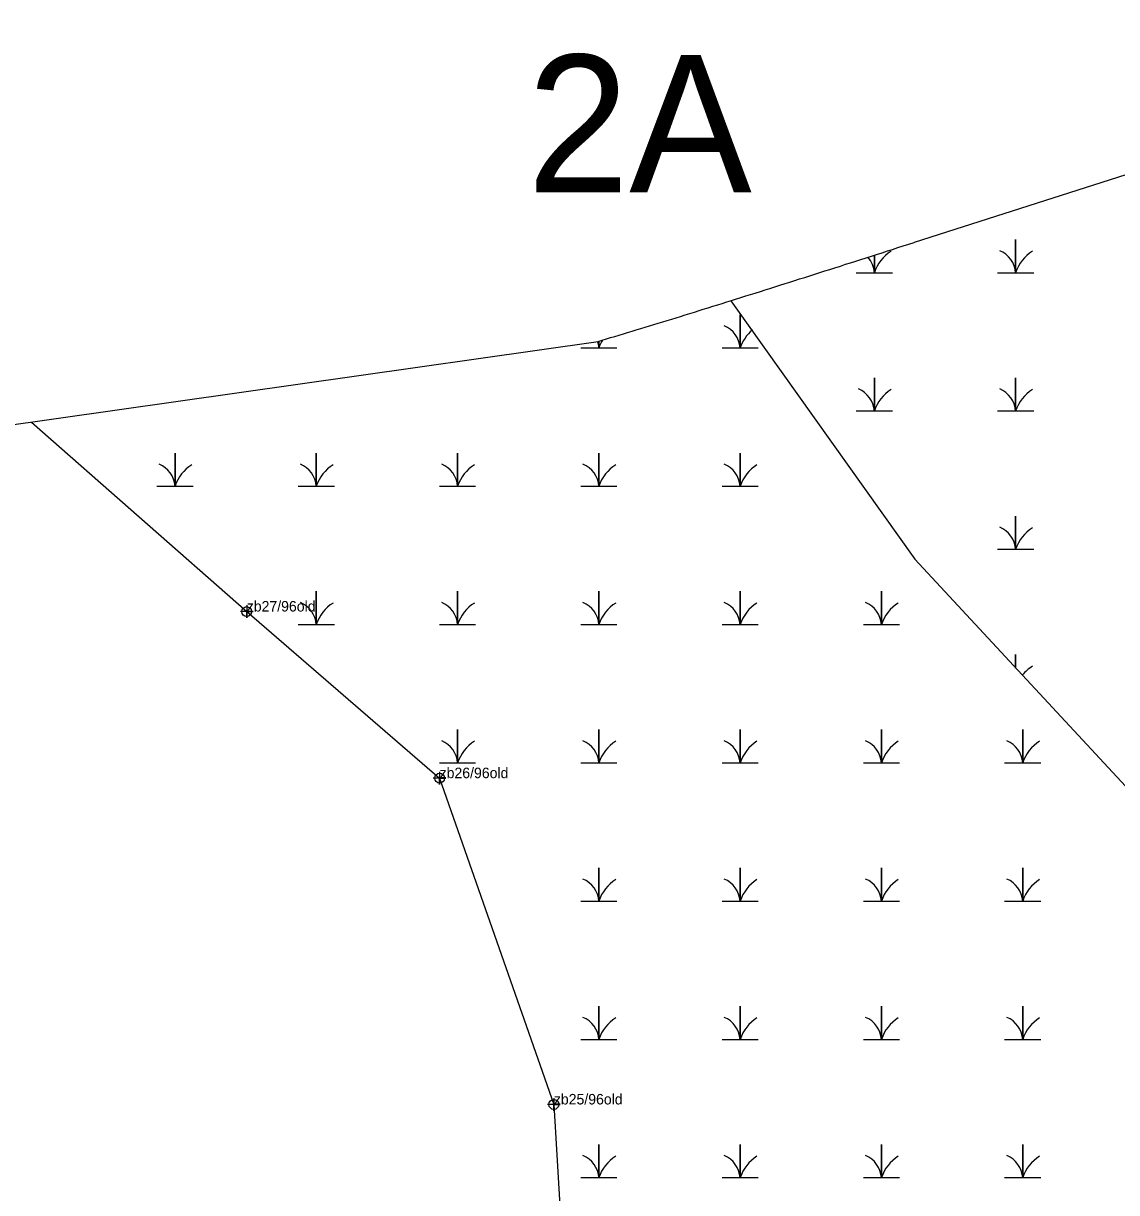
# Model space of a CAD drawing. Extents: x 2071991 to 2268989, y 436479 to 469629.
# Drawn here: x 2251156 to 2251676, y 439235 to 439791 of the extents above; entities that cross this region are included whole.
import ezdxf

# ---------------------------------------------------------------- set-up
doc = ezdxf.new("R2010")
doc.units = 0
for name, color, linetype in [('approx_PSA', 7, 'Continuous'), ('Default', 7, 'Continuous'), ('Exist Environmental Wetland Boundary', 7, 'Continuous'), ('Exist Environmental Wetland Boundary Cogo Comment', 7, 'Continuous'), ('Exist Environmental Wetland Boundary Cogo Point CELL', 7, 'Continuous'), ('Exist Hydro Jurisdictional Stream or Body of Water NEU Mitigable', 7, 'Continuous'), ('Exist Hydro Swamp or Marsh', 7, 'Continuous')]:
    doc.layers.add(name, color=color, linetype=linetype)

msp = doc.modelspace()

# ---------------------------------------------------------------- linework, layer by layer
at = {"layer": 'approx_PSA'}
for p, q in [((2251579.59, 439686.57), (2252759.53, 440064.53)), ((2251576.85, 439685.69), (2251579.42, 439686.51)), ((2251579.42, 439686.51), (2251579.59, 439686.57)), ((2251559.17, 439680.03), (2251561.58, 439680.8)), ((2251561.58, 439680.8), (2251564.15, 439681.62)), ((2251564.15, 439681.62), (2251566.72, 439682.44)), ((2251566.72, 439682.44), (2251569.13, 439683.21)), ((2251569.13, 439683.21), (2251571.7, 439684.04)), ((2251571.7, 439684.04), (2251574.28, 439684.86)), ((2251574.28, 439684.86), (2251576.85, 439685.69)), ((2251541.76, 439674.46), (2251544.33, 439675.28)), ((2251544.33, 439675.28), (2251546.86, 439676.09)), ((2251546.86, 439676.09), (2251549.21, 439676.84)), ((2251549.21, 439676.84), (2251551.67, 439677.63)), ((2251551.67, 439677.63), (2251554.08, 439678.4)), ((2251554.08, 439678.4), (2251556.6, 439679.2)), ((2251556.6, 439679.2), (2251559.17, 439680.03)), ((2251524.96, 439669.11), (2251527.37, 439669.88)), ((2251527.37, 439669.88), (2251529.78, 439670.64)), ((2251529.78, 439670.64), (2251532.13, 439671.39)), ((2251532.13, 439671.39), (2251534.59, 439672.18)), ((2251534.59, 439672.18), (2251536.95, 439672.93)), ((2251536.95, 439672.93), (2251539.3, 439673.68)), ((2251539.3, 439673.68), (2251541.76, 439674.46)), ((2251506.41, 439663.24), (2251508.65, 439663.94)), ((2251508.65, 439663.94), (2251510.79, 439664.62)), ((2251510.79, 439664.62), (2251513.2, 439665.38)), ((2251513.2, 439665.38), (2251515.6, 439666.14)), ((2251515.6, 439666.14), (2251518.01, 439666.91)), ((2251518.01, 439666.91), (2251520.25, 439667.62)), ((2251520.25, 439667.62), (2251522.61, 439668.36)), ((2251522.61, 439668.36), (2251524.96, 439669.11)), ((2251488.19, 439657.51), (2251490.38, 439658.19)), ((2251490.38, 439658.19), (2251492.62, 439658.9)), ((2251492.62, 439658.9), (2251494.86, 439659.6)), ((2251494.86, 439659.6), (2251497.05, 439660.29)), ((2251497.05, 439660.29), (2251499.41, 439661.03)), ((2251499.41, 439661.03), (2251501.65, 439661.73)), ((2251501.65, 439661.73), (2251503.84, 439662.42)), ((2251503.84, 439662.42), (2251506.41, 439663.24)), ((2251470.5, 439652.01), (2251472.69, 439652.69)), ((2251472.69, 439652.69), (2251474.94, 439653.38)), ((2251474.94, 439653.38), (2251477.13, 439654.06)), ((2251477.13, 439654.06), (2251479.15, 439654.69)), ((2251479.15, 439654.69), (2251481.39, 439655.39)), ((2251481.39, 439655.39), (2251483.75, 439656.13)), ((2251483.75, 439656.13), (2251486, 439656.82)), ((2251486, 439656.82), (2251488.19, 439657.51)), ((2251453.53, 439646.79), (2251455.6, 439647.43)), ((2251455.6, 439647.43), (2251457.63, 439648.05)), ((2251457.63, 439648.05), (2251459.82, 439648.72)), ((2251459.82, 439648.72), (2251462.02, 439649.39)), ((2251462.02, 439649.39), (2251464.21, 439650.07)), ((2251464.21, 439650.07), (2251466.28, 439650.71)), ((2251466.28, 439650.71), (2251468.31, 439651.33)), ((2251468.31, 439651.33), (2251470.5, 439652.01)), ((2251435.06, 439641.21), (2251437.09, 439641.82)), ((2251437.09, 439641.82), (2251439.12, 439642.43)), ((2251439.12, 439642.43), (2251441.14, 439643.04)), ((2251441.14, 439643.04), (2251443.17, 439643.65)), ((2251443.17, 439643.65), (2251445.25, 439644.28)), ((2251445.25, 439644.28), (2251447.28, 439644.89)), ((2251447.28, 439644.89), (2251449.47, 439645.56)), ((2251449.47, 439645.56), (2251451.5, 439646.18)), ((2251451.5, 439646.18), (2251453.53, 439646.79)), ((2250498.48, 439506.99), (2251429.14, 439639.44)), ((2251429.14, 439639.44), (2251431, 439640)), ((2251431, 439640), (2251433.03, 439640.6)), ((2251433.03, 439640.6), (2251435.06, 439641.21))]:
    msp.add_line(p, q, dxfattribs=at)
at = {"layer": 'Exist Environmental Wetland Boundary'}
msp.add_lwpolyline([(2251159.61, 439601.08), (2251261.98, 439510.93), (2251353.72, 439431.67), (2251408.06, 439276.46), (2251418.5, 439100.24), (2251356.47, 439015.14), (2251265.14, 438865.12), (2251366.82, 438844.78), (2251385.46, 438875.42), (2251556.91, 438853.1), (2251718.82, 438830.13), (2251868.44, 438639.97), (2251940.74, 438572.89), (2252098.49, 438426.72), (2252083.03, 438409.31), (2252090.25, 438402.8), (2252096.84, 438411.38), (2252129.61, 438370.68)], dxfattribs=at)
at = {"layer": 'Exist Environmental Wetland Boundary Cogo Point CELL'}
for points in [[(2251261.98, 439513.93), (2251261.98, 439507.93), (2251261.98, 439510.93), (2251264.98, 439510.93), (2251258.98, 439510.93)], [(2251353.72, 439434.67), (2251353.72, 439428.67), (2251353.72, 439431.67), (2251356.72, 439431.67), (2251350.72, 439431.67)], [(2251408.06, 439279.46), (2251408.06, 439273.46), (2251408.06, 439276.46), (2251411.06, 439276.46), (2251405.06, 439276.46)]]:
    msp.add_lwpolyline(points, dxfattribs=at)
for centre in [(2251261.98, 439510.93), (2251353.72, 439431.67), (2251408.06, 439276.46)]:
    msp.add_circle(centre, 2.34, dxfattribs=at)
at = {"layer": 'Exist Hydro Jurisdictional Stream or Body of Water NEU Mitigable'}
for p, q in [((2251492.31, 439658.8), (2251579.71, 439535.78)), ((2251579.71, 439535.78), (2251746.6, 439355.93))]:
    msp.add_line(p, q, dxfattribs=at)
at = {"layer": 'Exist Hydro Swamp or Marsh'}
for points in [[(2251619.11, 439672.1), (2251627.72, 439672.1), (2251627.72, 439687.88), (2251627.72, 439672.1), (2251636.32, 439672.1)], [(2251551.91, 439672.1), (2251560.51, 439672.1), (2251560.51, 439680.46)], [(2251560.51, 439680.46), (2251560.51, 439672.1), (2251569.11, 439672.1)], [(2251488.07, 439636.33), (2251496.67, 439636.33), (2251496.67, 439652.11), (2251496.67, 439636.33), (2251505.27, 439636.33)], [(2251420.86, 439636.33), (2251429.47, 439636.33), (2251429.47, 439639.54)], [(2251429.47, 439639.54), (2251429.47, 439636.33), (2251438.07, 439636.33)], [(2251551.91, 439606.32), (2251560.51, 439606.32), (2251560.51, 439622.1), (2251560.51, 439606.32), (2251569.11, 439606.32)], [(2251619.11, 439606.32), (2251627.72, 439606.32), (2251627.72, 439622.1), (2251627.72, 439606.32), (2251636.32, 439606.32)], [(2251219.25, 439570.55), (2251227.86, 439570.55), (2251227.86, 439586.33), (2251227.86, 439570.55), (2251236.46, 439570.55)], [(2251286.46, 439570.55), (2251295.06, 439570.55), (2251295.06, 439586.33), (2251295.06, 439570.55), (2251303.66, 439570.55)], [(2251353.66, 439570.55), (2251362.26, 439570.55), (2251362.26, 439586.33), (2251362.26, 439570.55), (2251370.86, 439570.55)], [(2251420.86, 439570.55), (2251429.47, 439570.55), (2251429.47, 439586.33), (2251429.47, 439570.55), (2251438.07, 439570.55)], [(2251488.07, 439570.55), (2251496.67, 439570.55), (2251496.67, 439586.33), (2251496.67, 439570.55), (2251505.27, 439570.55)], [(2251619.11, 439540.54), (2251627.72, 439540.54), (2251627.72, 439556.32), (2251627.72, 439540.54), (2251636.32, 439540.54)], [(2251286.46, 439504.77), (2251295.06, 439504.77), (2251295.06, 439520.55), (2251295.06, 439504.77), (2251303.66, 439504.77)], [(2251353.66, 439504.77), (2251362.26, 439504.77), (2251362.26, 439520.55), (2251362.26, 439504.77), (2251370.86, 439504.77)], [(2251420.86, 439504.77), (2251429.47, 439504.77), (2251429.47, 439520.55), (2251429.47, 439504.77), (2251438.07, 439504.77)], [(2251488.07, 439504.77), (2251496.67, 439504.77), (2251496.67, 439520.55), (2251496.67, 439504.77), (2251505.27, 439504.77)], [(2251555.27, 439504.77), (2251563.87, 439504.77), (2251563.87, 439520.55), (2251563.87, 439504.77), (2251572.47, 439504.77)], [(2251627.72, 439484.05), (2251627.72, 439490.54), (2251627.72, 439484.05)], [(2251353.66, 439438.99), (2251362.26, 439438.99), (2251362.26, 439454.77), (2251362.26, 439438.99), (2251370.86, 439438.99)], [(2251420.86, 439438.99), (2251429.47, 439438.99), (2251429.47, 439454.77), (2251429.47, 439438.99), (2251438.07, 439438.99)], [(2251488.07, 439438.99), (2251496.67, 439438.99), (2251496.67, 439454.77), (2251496.67, 439438.99), (2251505.27, 439438.99)], [(2251555.27, 439438.99), (2251563.87, 439438.99), (2251563.87, 439454.77), (2251563.87, 439438.99), (2251572.47, 439438.99)], [(2251622.47, 439438.99), (2251631.08, 439438.99), (2251631.08, 439454.77), (2251631.08, 439438.99), (2251639.68, 439438.99)], [(2251420.86, 439373.21), (2251429.47, 439373.21), (2251429.47, 439388.99), (2251429.47, 439373.21), (2251438.07, 439373.21)], [(2251488.07, 439373.21), (2251496.67, 439373.21), (2251496.67, 439388.99), (2251496.67, 439373.21), (2251505.27, 439373.21)], [(2251555.27, 439373.21), (2251563.87, 439373.21), (2251563.87, 439388.99), (2251563.87, 439373.21), (2251572.47, 439373.21)], [(2251622.47, 439373.21), (2251631.08, 439373.21), (2251631.08, 439388.99), (2251631.08, 439373.21), (2251639.68, 439373.21)], [(2251420.86, 439307.43), (2251429.47, 439307.43), (2251429.47, 439323.21), (2251429.47, 439307.43), (2251438.07, 439307.43)], [(2251488.07, 439307.43), (2251496.67, 439307.43), (2251496.67, 439323.21), (2251496.67, 439307.43), (2251505.27, 439307.43)], [(2251555.27, 439307.43), (2251563.87, 439307.43), (2251563.87, 439323.21), (2251563.87, 439307.43), (2251572.47, 439307.43)], [(2251622.47, 439307.43), (2251631.08, 439307.43), (2251631.08, 439323.21), (2251631.08, 439307.43), (2251639.68, 439307.43)], [(2251420.86, 439241.65), (2251429.47, 439241.65), (2251429.47, 439257.43), (2251429.47, 439241.65), (2251438.07, 439241.65)], [(2251488.07, 439241.65), (2251496.67, 439241.65), (2251496.67, 439257.43), (2251496.67, 439241.65), (2251505.27, 439241.65)], [(2251555.27, 439241.65), (2251563.87, 439241.65), (2251563.87, 439257.43), (2251563.87, 439241.65), (2251572.47, 439241.65)], [(2251622.47, 439241.65), (2251631.08, 439241.65), (2251631.08, 439257.43), (2251631.08, 439241.65), (2251639.68, 439241.65)]]:
    msp.add_lwpolyline(points, dxfattribs=at)
for centre, radius, start, end in [((2251578.75, 439666.04), 19.22, 122.1274, 161.6222), ((2251615.45, 439671.21), 12.3, 4.1403, 67.535), ((2251645.96, 439666.04), 19.22, 122.1274, 161.6222), ((2251548.25, 439671.21), 12.3, 4.1403, 42.0878), ((2251484.4, 439635.44), 12.3, 4.1403, 67.535), ((2251514.91, 439630.27), 19.22, 130.2593, 161.6222), ((2251417.2, 439635.44), 12.3, 4.1403, 18.7694), ((2251447.71, 439630.27), 19.22, 149.4467, 161.6222), ((2251548.25, 439605.43), 12.3, 4.1403, 67.535), ((2251578.75, 439600.26), 19.22, 122.1274, 161.6222), ((2251615.45, 439605.43), 12.3, 4.1403, 67.535), ((2251645.96, 439600.26), 19.22, 122.1274, 161.6222), ((2251215.59, 439569.66), 12.3, 4.1403, 67.535), ((2251246.1, 439564.49), 19.22, 122.1274, 161.6222), ((2251282.79, 439569.66), 12.3, 4.1403, 67.535), ((2251313.3, 439564.49), 19.22, 122.1274, 161.6222), ((2251350, 439569.66), 12.3, 4.1403, 67.535), ((2251380.51, 439564.49), 19.22, 122.1274, 161.6222), ((2251417.2, 439569.66), 12.3, 4.1403, 67.535), ((2251447.71, 439564.49), 19.22, 122.1274, 161.6222), ((2251484.4, 439569.66), 12.3, 4.1403, 67.535), ((2251514.91, 439564.49), 19.22, 122.1274, 161.6222), ((2251615.45, 439539.65), 12.3, 4.1403, 67.535), ((2251645.96, 439534.48), 19.22, 122.1274, 161.6222), ((2251282.79, 439503.88), 12.3, 4.1403, 67.535), ((2251313.3, 439498.71), 19.22, 122.1274, 161.6222), ((2251350, 439503.88), 12.3, 4.1403, 67.535), ((2251380.51, 439498.71), 19.22, 122.1274, 161.6222), ((2251417.2, 439503.88), 12.3, 4.1403, 67.535), ((2251447.71, 439498.71), 19.22, 122.1274, 161.6222), ((2251484.4, 439503.88), 12.3, 4.1403, 67.535), ((2251514.91, 439498.71), 19.22, 122.1274, 161.6222), ((2251551.61, 439503.88), 12.3, 4.1403, 67.535), ((2251582.12, 439498.71), 19.22, 122.1274, 161.6222), ((2251645.96, 439468.69), 19.22, 122.1274, 141.6256), ((2251350, 439438.1), 12.3, 4.1403, 67.535), ((2251380.51, 439432.93), 19.22, 122.1274, 161.6222), ((2251417.2, 439438.1), 12.3, 4.1403, 67.535), ((2251447.71, 439432.93), 19.22, 122.1274, 161.6222), ((2251484.4, 439438.1), 12.3, 4.1403, 67.535), ((2251514.91, 439432.93), 19.22, 122.1274, 161.6222), ((2251551.61, 439438.1), 12.3, 4.1403, 67.535), ((2251582.12, 439432.93), 19.22, 122.1274, 161.6222), ((2251618.81, 439438.1), 12.3, 4.1403, 67.535), ((2251649.32, 439432.93), 19.22, 122.1274, 161.6222), ((2251417.2, 439372.32), 12.3, 4.1403, 67.535), ((2251447.71, 439367.15), 19.22, 122.1274, 161.6222), ((2251484.4, 439372.32), 12.3, 4.1403, 67.535), ((2251514.91, 439367.15), 19.22, 122.1274, 161.6222), ((2251551.61, 439372.32), 12.3, 4.1403, 67.535), ((2251582.12, 439367.15), 19.22, 122.1274, 161.6222), ((2251618.81, 439372.32), 12.3, 4.1403, 67.535), ((2251649.32, 439367.15), 19.22, 122.1274, 161.6222), ((2251417.2, 439306.54), 12.3, 4.1403, 67.535), ((2251447.71, 439301.37), 19.22, 122.1274, 161.6222), ((2251484.4, 439306.54), 12.3, 4.1403, 67.535), ((2251514.91, 439301.37), 19.22, 122.1274, 161.6222), ((2251551.61, 439306.54), 12.3, 4.1403, 67.535), ((2251582.12, 439301.37), 19.22, 122.1274, 161.6222), ((2251618.81, 439306.54), 12.3, 4.1403, 67.535), ((2251649.32, 439301.37), 19.22, 122.1274, 161.6222), ((2251417.2, 439240.76), 12.3, 4.1403, 67.535), ((2251447.71, 439235.59), 19.22, 122.1274, 161.6222), ((2251484.4, 439240.76), 12.3, 4.1403, 67.535), ((2251514.91, 439235.59), 19.22, 122.1274, 161.6222), ((2251551.61, 439240.76), 12.3, 4.1403, 67.535), ((2251582.12, 439235.59), 19.22, 122.1274, 161.6222), ((2251618.81, 439240.76), 12.3, 4.1403, 67.535), ((2251649.32, 439235.59), 19.22, 122.1274, 161.6222)]:
    msp.add_arc(centre, radius, start, end, dxfattribs=at)

# ---------------------------------------------------------------- texts
at = {"layer": 'Default'}
msp.add_text('2A', height=65.34, dxfattribs=at).set_placement((2251395.31, 439710.38))
at = {"layer": 'Exist Environmental Wetland Boundary Cogo Comment'}
for s, p in [('zb27/96old', (2251261.98, 439510.93)), ('zb26/96old', (2251353.72, 439431.67)), ('zb25/96old', (2251408.06, 439276.46))]:
    msp.add_text(s, height=5, dxfattribs=at).set_placement(p)

doc.saveas('drawing.dxf')
